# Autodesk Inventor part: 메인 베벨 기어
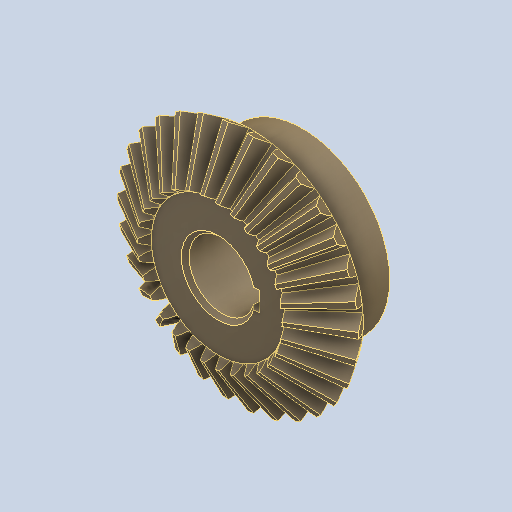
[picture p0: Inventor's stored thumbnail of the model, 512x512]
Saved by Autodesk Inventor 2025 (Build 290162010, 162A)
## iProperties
Created: 2024-07
Part Number: 메인 베벨 기어
Material: 강철, 탄소
Document SubType Name: Modeling
Designer: Admin
Density: 7.87 g/cm^3
Appearance: 기본값
Author: jhkim
Revision Number: 1
Sending System: Autodesk Inventor 2025
Preprocessor: ST-DEVELOPER v20
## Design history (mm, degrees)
feature "Solid1"
node "솔리드1"
